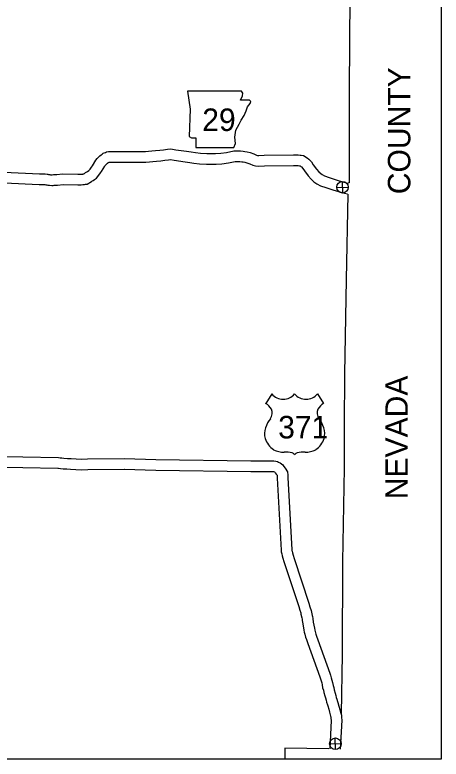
# Model space of a CAD drawing. Extents: x 79818 to 83933, y 50884 to 53307.
# Drawn here: x 81299.7 to 81460, y 52610.7 to 52890.4 of the extents above; entities that cross this region are included whole.
import ezdxf

# ---------------------------------------------------------------- set-up
doc = ezdxf.new("R2010")
doc.units = 0
for name, color, linetype in [('Level 15', 7, 'Continuous'), ('Level 2', 7, 'Continuous'), ('Level 21', 7, 'Continuous'), ('Level 22', 7, 'Continuous'), ('Level 26', 7, 'Continuous'), ('Level 30', 7, 'Continuous'), ('R_No Plot', 7, 'Continuous')]:
    doc.layers.add(name, color=color, linetype=linetype)

msp = doc.modelspace()

# ---------------------------------------------------------------- linework, layer by layer
at = {"layer": 'Level 15'}
for points in [[(81295.65, 52831.2), (81308.86, 52830.66), (81310.38, 52830.65), (81311.11, 52830.64), (81311.78, 52830.51), (81312.07, 52830.45), (81312.33, 52830.4), (81312.6, 52830.36), (81312.76, 52830.34), (81313.06, 52830.31), (81313.49, 52830.28), (81313.73, 52830.3), (81314.16, 52830.34), (81314.66, 52830.36), (81315.42, 52830.4), (81317.61, 52830.6), (81323.36, 52830.53), (81324.48, 52830.53), (81324.97, 52830.56), (81325.19, 52830.57), (81325.39, 52830.62), (81325.56, 52830.65), (81325.61, 52830.67), (81325.82, 52830.78), (81326.02, 52830.91), (81326.23, 52831.09), (81326.96, 52831.54), (81327.42, 52831.85), (81327.62, 52831.97), (81327.96, 52832.44), (81328.49, 52833.18), (81328.8, 52833.68), (81330.16, 52835.81), (81330.59, 52836.35), (81330.96, 52836.74), (81331.31, 52837.11), (81331.65, 52837.45), (81332.11, 52837.83), (81332.43, 52838.08), (81332.92, 52838.34), (81333.22, 52838.51), (81333.68, 52838.68), (81334.16, 52838.84), (81334.86, 52838.97), (81335.29, 52839), (81335.73, 52839.03), (81336.25, 52839.05), (81336.67, 52839.07), (81339.83, 52839.06)], [(81339.85, 52839.06), (81343.3, 52839.01), (81345.4, 52838.98), (81347.64, 52839.05), (81348.83, 52839.06), (81349.94, 52839.13), (81351.16, 52839.26), (81352.53, 52839.4), (81354.14, 52839.53), (81355.56, 52839.69), (81357, 52839.89), (81358.36, 52839.98), (81360.14, 52839.7), (81364.18, 52839.11), (81366, 52838.92), (81367.59, 52838.62), (81369.52, 52838.38), (81371.82, 52838.25), (81374.04, 52838.22), (81375.12, 52838.3), (81377.16, 52838.36), (81379.29, 52838.66), (81382.01, 52839.26), (81383.54, 52839.3), (81384.51, 52839.25), (81385.49, 52839.17), (81386.19, 52839.07), (81387.03, 52838.93), (81388.12, 52838.63), (81389.53, 52838.12), (81390.52, 52837.67), (81390.97, 52837.55), (81391.43, 52837.49), (81393.38, 52837.59), (81404.41, 52837.81), (81405.39, 52837.81), (81406.27, 52837.82), (81406.94, 52837.69), (81407.39, 52837.6), (81408.27, 52837.46), (81409.63, 52836.67), (81410.26, 52836.09), (81411.17, 52835.15), (81411.86, 52834.02), (81413.08, 52832.42), (81413.99, 52831.44), (81414.7, 52830.7), (81415.24, 52830.35), (81416.17, 52829.85), (81417.9, 52829.3), (81420.87, 52828.31), (81422.89, 52827.68), (81424.55, 52827.3), (81425.05, 52827.17)], [(81295.74, 52827.2), (81308.77, 52826.66), (81310.33, 52826.65), (81310.69, 52826.65), (81310.98, 52826.59), (81311.31, 52826.52), (81311.67, 52826.46), (81312.04, 52826.4), (81312.3, 52826.37), (81312.72, 52826.32), (81313.5, 52826.27), (81314.08, 52826.31), (81314.44, 52826.35), (81314.84, 52826.36), (81315.71, 52826.41), (81317.77, 52826.6), (81323.34, 52826.53), (81324.59, 52826.53), (81325.22, 52826.57), (81325.79, 52826.61), (81326.17, 52826.7), (81326.8, 52826.8), (81327.42, 52827.1), (81327.83, 52827.32), (81328.42, 52827.7), (81328.59, 52827.85), (81329.13, 52828.18), (81329.58, 52828.48), (81330.38, 52828.96), (81331.21, 52830.1), (81331.82, 52830.97), (81332.18, 52831.55), (81333.43, 52833.49), (81333.61, 52833.73), (81333.86, 52833.98), (81334.17, 52834.32), (81334.34, 52834.49), (81334.6, 52834.7), (81334.63, 52834.72), (81334.83, 52834.83), (81334.88, 52834.86), (81335.01, 52834.9), (81335.16, 52834.96), (81335.38, 52835), (81335.61, 52835.01), (81335.94, 52835.04), (81336.39, 52835.05), (81336.74, 52835.07), (81339.81, 52835.06)], [(81339.79, 52835.06), (81343.24, 52835.01), (81345.43, 52834.98), (81347.72, 52835.05), (81348.96, 52835.07), (81350.27, 52835.14), (81351.58, 52835.28), (81352.9, 52835.41), (81354.54, 52835.55), (81356.05, 52835.72), (81357.4, 52835.91), (81358.17, 52835.96), (81359.54, 52835.74), (81363.68, 52835.14), (81365.43, 52834.95), (81366.99, 52834.67), (81369.15, 52834.4), (81371.68, 52834.25), (81374.17, 52834.22), (81375.33, 52834.3), (81377.5, 52834.37), (81380, 52834.72), (81382.49, 52835.27), (81383.49, 52835.3), (81384.25, 52835.26), (81385.05, 52835.2), (81385.56, 52835.12), (81386.16, 52835.02), (81386.91, 52834.81), (81388.02, 52834.41), (81389.15, 52833.9), (81390.19, 52833.61), (81391.28, 52833.48), (81393.52, 52833.59), (81404.45, 52833.81), (81405.41, 52833.81), (81405.91, 52833.82), (81406.15, 52833.77), (81406.67, 52833.66), (81406.91, 52833.63), (81407.24, 52833.43), (81407.47, 52833.22), (81407.99, 52832.68), (81408.55, 52831.76), (81410.01, 52829.85), (81411.08, 52828.69), (81412.15, 52827.58), (81413.22, 52826.9), (81414.6, 52826.15), (81416.66, 52825.5), (81419.64, 52824.5), (81421.85, 52823.82), (81423.58, 52823.41), (81424.8, 52823.09)], [(81284.86, 52724.55), (81302.68, 52724.34), (81316.1, 52724.05), (81316.74, 52723.96), (81317.27, 52723.86), (81318.02, 52723.82), (81319.5, 52723.72), (81320.87, 52723.65), (81322.75, 52723.53), (81324.83, 52723.45), (81327, 52723.55), (81340.83, 52723.61)], [(81340.9, 52723.61), (81352.73, 52723.25), (81388.41, 52722.73), (81396.56, 52722.79), (81397.07, 52722.82), (81397.85, 52722.72), (81398.42, 52722.51), (81398.87, 52722.3), (81399.48, 52722.05), (81400.41, 52721.33), (81400.86, 52720.65), (81401.29, 52720.08), (81402.14, 52718.69), (81402.26, 52717.43), (81402.31, 52716.54), (81403.84, 52689.4), (81403.84, 52689.03), (81403.89, 52688.82), (81404.07, 52688.2), (81404.33, 52687.36), (81404.65, 52686.13), (81410.19, 52669.25), (81410.65, 52667.91), (81411.09, 52666.58), (81411.19, 52665.87), (81411.42, 52664.72), (81411.56, 52664.26), (81411.7, 52663.49), (81411.9, 52662.18), (81412.3, 52659.86), (81412.43, 52659.2), (81412.56, 52658.64), (81412.85, 52657.66), (81413.08, 52656.87), (81413.57, 52655.57), (81418.07, 52642.98), (81418.37, 52642.18), (81418.67, 52641.29), (81418.91, 52640.41), (81419.16, 52639.46), (81419.32, 52638.4), (81419.58, 52637.63), (81419.77, 52636.74), (81420.18, 52635.43), (81420.35, 52634.6), (81420.55, 52633.88), (81420.73, 52633.22), (81420.98, 52632.39), (81421.14, 52631.95), (81421.56, 52630.64), (81421.93, 52629.3), (81422.23, 52627.98), (81422.49, 52627.24), (81422.5, 52626.33), (81422.59, 52625.3), (81422.06, 52614.43)], [(81285.16, 52720.55), (81302.62, 52720.34), (81315.8, 52720.05), (81316.11, 52720.01), (81316.79, 52719.88), (81317.78, 52719.83), (81319.26, 52719.73), (81320.64, 52719.66), (81322.54, 52719.53), (81324.84, 52719.44), (81327.1, 52719.55), (81340.85, 52719.61)], [(81340.78, 52719.61), (81352.64, 52719.25), (81388.39, 52718.73), (81396.66, 52718.79), (81396.89, 52718.8), (81397.29, 52718.62), (81397.45, 52718.56), (81397.61, 52718.32), (81397.99, 52717.82), (81398.25, 52717.39), (81398.27, 52717.12), (81398.32, 52716.31), (81399.84, 52689.27), (81399.85, 52688.54), (81400.02, 52687.82), (81400.23, 52687.06), (81400.49, 52686.25), (81400.81, 52685.01), (81406.4, 52667.99), (81406.85, 52666.64), (81407.18, 52665.65), (81407.25, 52665.2), (81407.53, 52663.76), (81407.66, 52663.32), (81407.75, 52662.83), (81407.95, 52661.53), (81408.37, 52659.13), (81408.52, 52658.36), (81408.69, 52657.61), (81409.01, 52656.54), (81409.28, 52655.6), (81409.82, 52654.19), (81414.31, 52641.62), (81414.6, 52640.85), (81414.84, 52640.12), (81415.05, 52639.37), (81415.24, 52638.64), (81415.42, 52637.47), (81415.72, 52636.56), (81415.91, 52635.72), (81416.3, 52634.42), (81416.46, 52633.67), (81416.69, 52632.83), (81416.89, 52632.1), (81417.19, 52631.12), (81417.36, 52630.66), (81417.73, 52629.49), (81418.05, 52628.33), (81418.37, 52626.88), (81418.5, 52626.53), (81418.5, 52626.13), (81418.58, 52625.22), (81418.06, 52614.61)]]:
    msp.add_lwpolyline(points, dxfattribs=at)
at = {"layer": 'Level 2'}
for points in [[(81425.87, 52915.36), (81425.62, 52897.66), (81425.44, 52862.17), (81425.38, 52827.21), (81425.15, 52827.24)], [(81424.87, 52822.98), (81424.25, 52790.87), (81423.63, 52755.5), (81423.51, 52735.89)], [(81423.51, 52735.89), (81423.54, 52720.01), (81422.93, 52684.91), (81422.75, 52649.98), (81422.42, 52627.66)], [(81417.78, 52614.58), (81401.25, 52614.86), (81401.21, 52610.7)]]:
    msp.add_lwpolyline(points, dxfattribs=at)
at = {"layer": 'Level 21'}
msp.add_lwpolyline([(81364.62, 52861.75), (81365.63, 52854.99), (81365.18, 52844.72), (81366.08, 52844.16), (81367.77, 52844.16), (81367.77, 52840.55), (81381.99, 52840.55), (81382.66, 52842.02), (81382.44, 52844.39), (81382.78, 52847.09), (81384.02, 52849.24), (81384.81, 52850.81), (81385.93, 52852.51), (81386.61, 52854.31), (81387.17, 52855.78), (81388.19, 52857.02), (81388.41, 52857.81), (81387.96, 52858.37), (81384.47, 52858.37), (81385.26, 52859.95), (81385.37, 52860.96), (81384.9, 52861.74)], close=True, dxfattribs=at)
at = {"layer": 'Level 22'}
for p, q in [((81396.3, 52747.93), (81393.99, 52744.36)), ((81413.46, 52747.93), (81415.77, 52744.36))]:
    msp.add_line(p, q, dxfattribs=at)
for centre, radius, start, end in [((81400.6, 52751.54), 5.62, 220.075, 319.6701), ((81409.16, 52751.54), 5.62, 220.3299, 319.925), ((81390.98, 52739.18), 6, 30.7809, 59.9883), ((81392.3, 52740.76), 4.11, 328.8105, 21.2108), ((81417.46, 52740.76), 4.11, 158.7892, 211.1895), ((81418.78, 52739.18), 6, 120.0117, 149.2191), ((81403.05, 52732.33), 9.59, 138.9565, 162.6913), ((81406.72, 52732.33), 9.59, 17.3087, 41.0435), ((81399.88, 52733.12), 6.34, 160.9576, 197.3819), ((81409.88, 52733.12), 6.34, 342.6181, 19.0424), ((81400.91, 52733.14), 7.33, 195.1074, 237.1312), ((81408.85, 52733.14), 7.33, 302.8688, 344.8926), ((81401.05, 52735.44), 9.41, 244.0771, 269.5779), ((81401.27, 52708.79), 17.24, 81.1942, 90.9539), ((81403.42, 52724.25), 1.65, 28.0342, 72.9864), ((81406.34, 52724.25), 1.65, 107.0136, 151.9658), ((81408.5, 52708.79), 17.24, 89.0461, 98.8058), ((81408.71, 52735.44), 9.41, 270.4221, 295.9229)]:
    msp.add_arc(centre, radius, start, end, dxfattribs=at)
at = {"layer": 'Level 26'}
for p, q in [((81422.95, 52823.43), (81422.85, 52827.77)), ((81420.73, 52825.55), (81425.07, 52825.65)), ((81418.04, 52616.42), (81422.38, 52616.52)), ((81420.26, 52614.3), (81420.16, 52618.64))]:
    msp.add_line(p, q, dxfattribs=at)
for centre in [(81422.9, 52825.6), (81420.21, 52616.47)]:
    msp.add_circle(centre, 2.17, dxfattribs=at)
at = {"layer": 'R_No Plot'}
msp.add_lwpolyline([(80798.6, 53193.52), (81459.98, 53193.52), (81459.98, 52610.7), (80798.6, 52610.7)], close=True, dxfattribs=at)
msp.add_lwpolyline([(80798.6, 53193.52), (81459.98, 53193.52), (81459.98, 52610.7), (80798.6, 52610.7)], close=True, dxfattribs=at)

# ---------------------------------------------------------------- texts
at = {"layer": 'Level 21'}
msp.add_text('29', height=8.448, dxfattribs=at).set_placement((81370.14, 52846.74))
at = {"layer": 'Level 22'}
msp.add_text('371', height=8.448, dxfattribs=at).set_placement((81398.69, 52731.21))
at = {"layer": 'Level 30'}
for s, p in [('COUNTY', (81448.4, 52822.97)), ('NEVADA', (81447.45, 52708.35))]:
    msp.add_text(s, height=8.448, rotation=90, dxfattribs=at).set_placement(p)

doc.saveas('drawing.dxf')
